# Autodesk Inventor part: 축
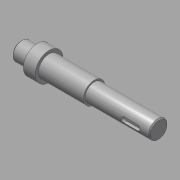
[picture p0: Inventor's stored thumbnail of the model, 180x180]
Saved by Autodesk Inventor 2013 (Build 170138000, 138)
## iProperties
Created: 2015-09
Part Number: 축
Material: 강철, 연강
Document SubType Name: Modeling
Designer: mduedu
Density: 7.86 g/cm^3
Mass: 263.424 g
Surface Area: 86.4309 cm^2
Volume: 33.5145 cm^3
Author: mduedu
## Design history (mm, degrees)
sketch "스케치1"
  geometry: L1 (-69, 0)-(69, 0); L2 (-69, 0)-(-69, 8.5); L3 (-69, 8.5)-(-54, 8.5); L4 (-54, 8.5)-(-54, 13); L5 (-54, 13)-(-43, 13); L6 (-43, 13)-(-43, 10); L7 (-43, 10)-(-1, 10); L8 (-1, 10)-(-1, 8.5); L9 (-1, 8.5)-(69, 8.5); L10 (69, 8.5)-(69, 0); 2 further points
  constraints: 20 end point, 5 parallel, 2 horizontal, 2 perpendicular, 1 coincident, 1 midpoint, 1 vertical
  dimensions: "d0" = 138 distance of L1.start L1.end; "d2" = 11 distance of L4.end L5.end; "d3" = 42 distance of L6.end L7.end; "d4" = 70 distance of L8.end L9.end; "d5" = 17 diameter of L3 L1; "d6" = 17 diameter of L9 L1; "d7" = 20 diameter of L7 L1; "d8" = 26 diameter of L5 L1
revolve "회전1" sketch "스케치1" stored, may be unused: angle "d9" = 90 deg
node "작업 평면1"
sketch "스케치2"
  geometry: L1 (10.5, 2.5)-(23.5, 2.5); L2 (23.5, -2.5)-(10.5, -2.5); L3 (10.5, 2.5)-(23.5, -2.5); L4 (23.5, 2.5)-(10.5, -2.5); L5 (35, -8.5)-(35, 8.5) reference; A1 r 2.5 centre (10.5, 0) between (10.5, 2.5) and (10.5, -2.5); A2 r 2.5 centre (23.5, 0) between (23.5, -2.5) and (23.5, 2.5); 2 further points
  constraints: 8 end point, 4 point on circle, 4 tangent, 2 centre point, 2 midpoint, 1 horizontal, 1 horizontal alignment, 1 parallel
  dimensions: "d10" = 18 dimension on A2 A1; "d12" = 9 distance edge to line of A2 L5; "d13" = 5 distance between parallel lines of L2 L1
extrude "돌출1" cut sketch "스케치2" distance "d14" = 3; taper "d15" = 0 deg
node "작업 평면2"
sketch "스케치4"
  geometry: L1 (7, -3)-(-9, -3); L2 (-9, 3)-(7, 3); L3 (-21, 10)-(-21, -10) reference; A1 r 3 centre (-9, 0) between (-9, 3) and (-9, -3); A2 r 3 centre (7, 0) between (7, -3) and (7, 3); 1 further point
  constraints: 4 end point, 4 point on circle, 4 tangent, 2 centre point, 1 horizontal, 1 horizontal alignment, 1 parallel
  dimensions: "d16" = 22 dimension on A1 A2; "d18" = 6 distance between parallel lines of L2 L1; "d19" = 9 distance edge to line of A1 L3
extrude "돌출2" cut sketch "스케치4" distance "d20" = 3.5; taper "d21" = 0 deg
sketch "스케치5"
  geometry: L1 (-1, 8.5)-(69, 8.5) reference; L2 (-1, -8.5)-(69, -8.5) reference; L3 (42, 8.5)-(42, -8.5); L4 (42, -6.5)-(40, -8.5); L5 (42, -8.5)-(40, -8.5); L6 (42, -8.5)-(42, -6.5); L7 (-1, -10)-(-1, 10) reference; 1 further point
  constraints: 8 end point, 4 point on line, 1 collinear, 1 perpendicular
  dimensions: "d22" = 4 diameter of L4.end L3; "d24" = 45 deg angle of L3 L4; "d26" = 43 distance between parallel lines of L3 L7
revolve "회전2" sketch "스케치5" stored, may be unused: angle "d27" = 90 deg
chamfer "모따기1" distance "d28" = 1; stored, may be unused: second distance "d29" = 2, angle "d30" = 45 deg
sketch "스케치6"
  geometry: L1 (42, -6.5)-(40, -8.5) reference; L2 (42, -6.5)-(44, -8.5) reference; 2 further points
  constraints: 1 coincident
node "솔리드1"
